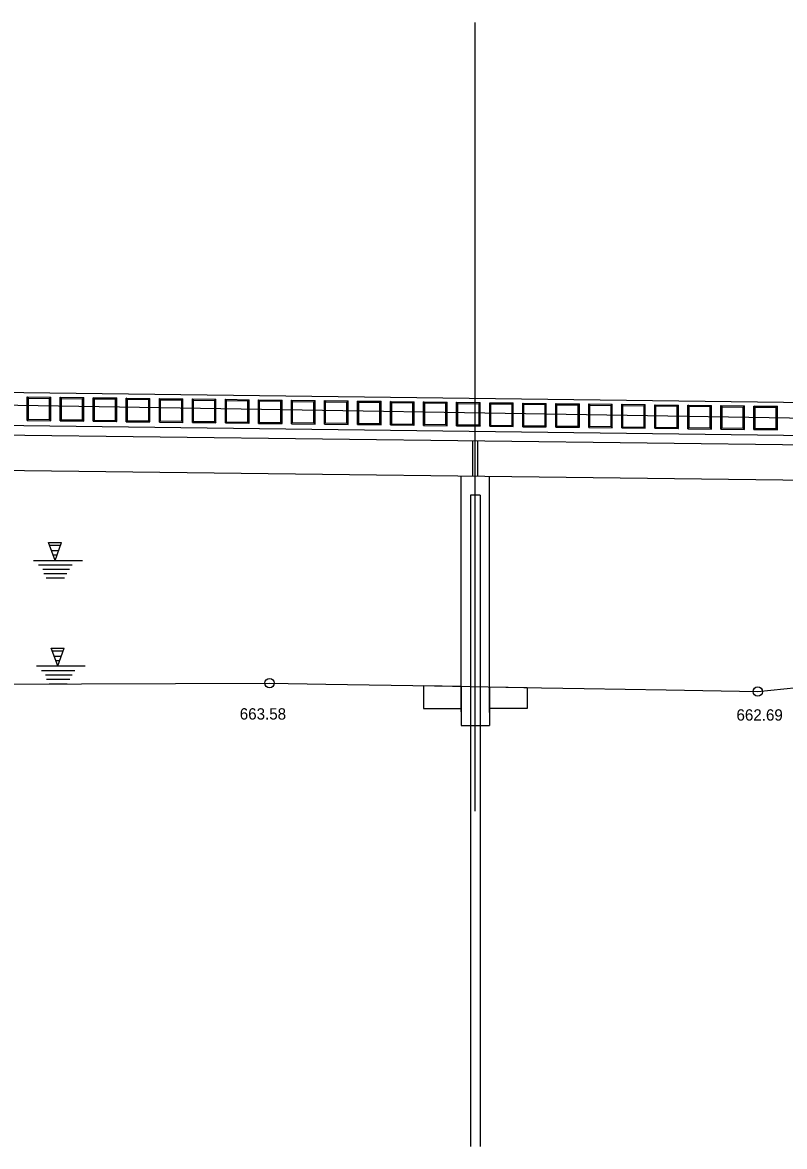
# Model space of a CAD drawing. Extents: x -845213 to 595816, y -257022 to 229056.
# Drawn here: x 595562.8 to 595643.5, y 228641.3 to 228760.5 of the extents above; entities that cross this region are included whole.
import ezdxf

# ---------------------------------------------------------------- set-up
doc = ezdxf.new("R2010")
doc.units = 0
for name, color, linetype in [('B_CL', 7, 'Continuous'), ('B_CONC', 7, 'Continuous'), ('B_CONC_HIDDEN', 7, 'Continuous'), ('B_GROUNDLINE', 7, 'Continuous'), ('B_MISC', 7, 'Continuous'), ('B_PATTERN', 7, 'Continuous'), ('B_PILES_HIDDEN', 7, 'Continuous'), ('B_SCREEN', 7, 'Continuous'), ('E_STRUCT', 7, 'Continuous'), ('P_E_PROF', 7, 'Continuous'), ('P_PROF', 7, 'Continuous')]:
    doc.layers.add(name, color=color, linetype=linetype)

msp = doc.modelspace()

# ---------------------------------------------------------------- linework, layer by layer
at = {"layer": 'B_CL'}
msp.add_line((595610.79, 228676.87), (595610.79, 228760.49), dxfattribs=at)
at = {"layer": 'B_CONC'}
for p, q in [((595399.25, 228723.31), (595719.75, 228719.29)), ((595421.62, 228718.53), (595696.95, 228715.07)), ((595610.52, 228712.41), (595610.52, 228716.16)), ((595611.06, 228712.4), (595611.06, 228716.15)), ((595417.81, 228714.82), (595700.75, 228711.28)), ((595609.29, 228687.41), (595609.29, 228712.39)), ((595612.29, 228687.35), (595612.29, 228712.36))]:
    msp.add_line(p, q, dxfattribs=at)
at = {"layer": 'B_CONC_HIDDEN'}
for p, q in [((595609.29, 228690.1), (595609.29, 228685.97)), ((595612.29, 228690.05), (595612.29, 228685.97)), ((595609.29, 228685.97), (595612.29, 228685.97))]:
    msp.add_line(p, q, dxfattribs=at)
at = {"layer": 'B_GROUNDLINE'}
for p, q in [((595566.26, 228703.47), (595565.58, 228705.35)), ((595565.58, 228705.35), (595566.95, 228705.35)), ((595565.68, 228705.08), (595566.85, 228705.08)), ((595566.26, 228703.47), (595566.95, 228705.35)), ((595565.89, 228704.5), (595566.61, 228704.5)), ((595566.07, 228704.05), (595566.47, 228704.05)), ((595563.99, 228703.47), (595569.18, 228703.47)), ((595564.52, 228703), (595568.07, 228703)), ((595564.96, 228702.53), (595567.8, 228702.53)), ((595565.06, 228702.06), (595567.52, 228702.06)), ((595565.33, 228701.6), (595567.25, 228701.6)), ((595566.55, 228692.27), (595565.86, 228694.15)), ((595565.86, 228694.15), (595567.23, 228694.15)), ((595565.96, 228693.88), (595567.13, 228693.88)), ((595566.17, 228693.3), (595566.9, 228693.3)), ((595566.55, 228692.27), (595567.23, 228694.15)), ((595564.28, 228692.27), (595569.46, 228692.27)), ((595566.36, 228692.85), (595566.75, 228692.85)), ((595564.81, 228691.8), (595568.35, 228691.8)), ((595565.25, 228691.33), (595568.08, 228691.33)), ((595565.35, 228690.86), (595567.81, 228690.86)), ((595565.62, 228690.39), (595567.54, 228690.39))]:
    msp.add_line(p, q, dxfattribs=at)
at = {"layer": 'B_MISC'}
for centre in [(595588.99, 228690.45), (595640.72, 228689.56)]:
    msp.add_circle(centre, 0.5, dxfattribs=at)
at = {"layer": 'B_PATTERN'}
for points in [[(595609.29, 228690.1), (595605.29, 228690.17), (595605.29, 228687.76), (595609.29, 228687.77)], [(595612.29, 228687.77), (595612.29, 228690.05), (595616.29, 228689.98), (595616.29, 228687.77)]]:
    msp.add_lwpolyline(points, close=True, dxfattribs=at)
at = {"layer": 'B_PILES_HIDDEN'}
for p, q in [((595610.29, 228710.4), (595611.29, 228710.4)), ((595610.29, 228710.37), (595610.29, 228641.33)), ((595611.29, 228710.37), (595611.29, 228641.33))]:
    msp.add_line(p, q, dxfattribs=at)
at = {"layer": 'B_SCREEN'}
for p, q in [((595563.31, 228718.3), (595563.31, 228720.8)), ((595563.31, 228720.8), (595565.81, 228720.77)), ((595563.43, 228720.67), (595563.31, 228720.8)), ((595563.43, 228720.67), (595565.68, 228720.64)), ((595563.43, 228718.42), (595563.43, 228720.67)), ((595565.68, 228720.64), (595565.81, 228720.77)), ((595565.68, 228718.39), (595565.68, 228720.64)), ((595565.81, 228718.27), (595565.81, 228720.77)), ((595566.81, 228718.26), (595566.81, 228720.76)), ((595566.81, 228720.76), (595569.31, 228720.72)), ((595566.93, 228720.63), (595566.81, 228720.76)), ((595566.93, 228720.63), (595569.18, 228720.6)), ((595566.93, 228718.38), (595566.93, 228720.63)), ((595569.18, 228720.6), (595569.31, 228720.72)), ((595569.18, 228718.35), (595569.18, 228720.6)), ((595569.31, 228718.22), (595569.31, 228720.72)), ((595570.31, 228718.21), (595570.31, 228720.71)), ((595570.31, 228720.71), (595572.81, 228720.68)), ((595570.43, 228720.58), (595570.31, 228720.71)), ((595570.43, 228720.58), (595572.68, 228720.56)), ((595570.43, 228718.34), (595570.43, 228720.58)), ((595572.68, 228720.56), (595572.81, 228720.68)), ((595572.68, 228718.31), (595572.68, 228720.56)), ((595572.81, 228718.18), (595572.81, 228720.68)), ((595573.81, 228718.17), (595573.81, 228720.67)), ((595573.81, 228720.67), (595576.31, 228720.64)), ((595573.93, 228720.54), (595573.81, 228720.67)), ((595573.93, 228720.54), (595576.18, 228720.51)), ((595573.93, 228718.29), (595573.93, 228720.54)), ((595576.18, 228720.51), (595576.31, 228720.64)), ((595576.18, 228718.26), (595576.18, 228720.51)), ((595576.31, 228718.14), (595576.31, 228720.64)), ((595577.31, 228718.12), (595577.31, 228720.62)), ((595577.31, 228720.62), (595579.81, 228720.59)), ((595577.43, 228720.5), (595577.31, 228720.62)), ((595577.43, 228720.5), (595579.68, 228720.47)), ((595577.43, 228718.25), (595577.43, 228720.5)), ((595579.68, 228720.47), (595579.81, 228720.59)), ((595579.68, 228718.22), (595579.68, 228720.47)), ((595579.81, 228718.09), (595579.81, 228720.59)), ((595580.81, 228718.08), (595580.81, 228720.58)), ((595580.81, 228720.58), (595583.31, 228720.55)), ((595580.93, 228720.45), (595580.81, 228720.58)), ((595580.93, 228720.45), (595583.18, 228720.43)), ((595580.93, 228718.2), (595580.93, 228720.45)), ((595583.18, 228720.43), (595583.31, 228720.55)), ((595583.31, 228718.05), (595583.31, 228720.55)), ((595584.31, 228718.04), (595584.31, 228720.54)), ((595584.31, 228720.54), (595586.81, 228720.5)), ((595584.43, 228720.41), (595584.31, 228720.54)), ((595586.68, 228720.38), (595586.81, 228720.5)), ((595586.81, 228718), (595586.81, 228720.5)), ((595587.81, 228717.99), (595587.81, 228720.49)), ((595587.81, 228720.49), (595590.31, 228720.46)), ((595587.93, 228720.37), (595587.81, 228720.49)), ((595590.18, 228720.34), (595590.31, 228720.46)), ((595590.31, 228717.96), (595590.31, 228720.46)), ((595591.31, 228717.95), (595591.31, 228720.45)), ((595591.31, 228720.45), (595593.81, 228720.42)), ((595591.43, 228720.32), (595591.31, 228720.45)), ((595583.18, 228718.18), (595583.18, 228720.43)), ((595584.43, 228720.41), (595586.68, 228720.38)), ((595584.43, 228718.16), (595584.43, 228720.41)), ((595586.68, 228718.13), (595586.68, 228720.38)), ((595587.93, 228720.37), (595590.18, 228720.34)), ((595587.93, 228718.12), (595587.93, 228720.37)), ((595590.18, 228718.09), (595590.18, 228720.34)), ((595591.43, 228720.32), (595593.68, 228720.29)), ((595591.43, 228718.07), (595591.43, 228720.32)), ((595593.68, 228720.29), (595593.81, 228720.42)), ((595593.68, 228718.04), (595593.68, 228720.29)), ((595593.81, 228717.92), (595593.81, 228720.42)), ((595594.81, 228717.9), (595594.81, 228720.4)), ((595594.81, 228720.4), (595597.31, 228720.37)), ((595594.81, 228720.4), (595594.93, 228720.28)), ((595594.93, 228720.28), (595597.18, 228720.25)), ((595594.93, 228718.03), (595594.93, 228720.28)), ((595597.18, 228720.25), (595597.31, 228720.37)), ((595597.18, 228718), (595597.18, 228720.25)), ((595597.31, 228717.87), (595597.31, 228720.37)), ((595598.31, 228717.86), (595598.31, 228720.36)), ((595598.31, 228720.36), (595600.81, 228720.33)), ((595598.43, 228720.23), (595598.31, 228720.36)), ((595598.43, 228720.23), (595600.68, 228720.21)), ((595598.43, 228717.98), (595598.43, 228720.23)), ((595600.68, 228720.21), (595600.81, 228720.33)), ((595600.68, 228717.96), (595600.68, 228720.21)), ((595600.81, 228717.83), (595600.81, 228720.33)), ((595601.81, 228717.82), (595601.81, 228720.32)), ((595601.81, 228720.32), (595604.31, 228720.29)), ((595601.93, 228720.19), (595601.81, 228720.32)), ((595601.93, 228720.19), (595604.18, 228720.16)), ((595601.93, 228717.94), (595601.93, 228720.19)), ((595604.18, 228720.16), (595604.31, 228720.29)), ((595604.18, 228717.91), (595604.18, 228720.16)), ((595604.31, 228717.79), (595604.31, 228720.29)), ((595605.31, 228717.77), (595605.31, 228720.27)), ((595605.31, 228720.27), (595607.81, 228720.24)), ((595605.43, 228720.15), (595605.31, 228720.27)), ((595605.43, 228720.15), (595607.68, 228720.12)), ((595605.43, 228717.9), (595605.43, 228720.15)), ((595607.68, 228720.12), (595607.81, 228720.24)), ((595607.68, 228717.87), (595607.68, 228720.12)), ((595607.81, 228717.74), (595607.81, 228720.24)), ((595608.81, 228717.73), (595608.81, 228720.23)), ((595608.81, 228720.23), (595611.31, 228720.2)), ((595608.93, 228720.1), (595608.81, 228720.23)), ((595608.93, 228720.1), (595611.18, 228720.07)), ((595608.93, 228717.85), (595608.93, 228720.1)), ((595611.18, 228720.07), (595611.31, 228720.2)), ((595611.18, 228717.82), (595611.18, 228720.07)), ((595611.31, 228717.7), (595611.31, 228720.2)), ((595612.31, 228717.68), (595612.31, 228720.18)), ((595612.31, 228720.18), (595614.81, 228720.15)), ((595612.43, 228720.06), (595612.31, 228720.18)), ((595612.43, 228720.06), (595614.68, 228720.03)), ((595612.43, 228717.81), (595612.43, 228720.06)), ((595614.68, 228720.03), (595614.81, 228720.15)), ((595614.68, 228717.78), (595614.68, 228720.03)), ((595614.81, 228717.65), (595614.81, 228720.15)), ((595615.81, 228717.64), (595615.81, 228720.14)), ((595615.81, 228720.14), (595618.31, 228720.11)), ((595615.93, 228720.01), (595615.81, 228720.14)), ((595615.93, 228720.01), (595618.18, 228719.99)), ((595615.93, 228717.76), (595615.93, 228720.01)), ((595618.18, 228719.99), (595618.31, 228720.11)), ((595618.18, 228717.74), (595618.18, 228719.99)), ((595618.31, 228717.61), (595618.31, 228720.11)), ((595619.31, 228717.6), (595619.31, 228720.1)), ((595619.31, 228720.1), (595621.81, 228720.07)), ((595619.43, 228719.97), (595619.31, 228720.1)), ((595619.43, 228719.97), (595621.68, 228719.94)), ((595619.43, 228717.72), (595619.43, 228719.97)), ((595621.68, 228719.94), (595621.81, 228720.07)), ((595621.68, 228717.69), (595621.68, 228719.94)), ((595621.81, 228717.57), (595621.81, 228720.07)), ((595622.81, 228717.55), (595622.81, 228720.05)), ((595622.81, 228720.05), (595625.3, 228720.02)), ((595622.93, 228719.93), (595622.81, 228720.05)), ((595622.93, 228719.93), (595625.18, 228719.9)), ((595622.93, 228717.68), (595622.93, 228719.93)), ((595625.18, 228719.9), (595625.3, 228720.02)), ((595625.18, 228717.65), (595625.18, 228719.9)), ((595625.3, 228717.52), (595625.3, 228720.02)), ((595626.3, 228717.51), (595626.3, 228720.01)), ((595626.3, 228720.01), (595628.8, 228719.98)), ((595626.43, 228719.88), (595626.3, 228720.01)), ((595626.43, 228719.88), (595628.68, 228719.85)), ((595626.43, 228717.63), (595626.43, 228719.88)), ((595628.68, 228719.85), (595628.8, 228719.98)), ((595628.68, 228717.6), (595628.68, 228719.85)), ((595628.8, 228717.48), (595628.8, 228719.98)), ((595629.8, 228717.47), (595629.8, 228719.97)), ((595629.8, 228719.97), (595632.3, 228719.93)), ((595629.93, 228719.84), (595629.8, 228719.97)), ((595629.93, 228719.84), (595632.18, 228719.81)), ((595629.93, 228717.59), (595629.93, 228719.84)), ((595632.18, 228719.81), (595632.3, 228719.93)), ((595632.18, 228717.56), (595632.18, 228719.81)), ((595632.3, 228717.43), (595632.3, 228719.93)), ((595633.3, 228717.42), (595633.3, 228719.92)), ((595633.3, 228719.92), (595635.8, 228719.89)), ((595633.43, 228719.8), (595633.3, 228719.92)), ((595633.43, 228719.8), (595635.68, 228719.77)), ((595633.43, 228717.55), (595633.43, 228719.8)), ((595635.68, 228719.77), (595635.8, 228719.89)), ((595635.68, 228717.52), (595635.68, 228719.77)), ((595635.8, 228717.39), (595635.8, 228719.89)), ((595636.8, 228717.38), (595636.8, 228719.88)), ((595636.93, 228719.75), (595636.8, 228719.88)), ((595636.8, 228719.88), (595639.3, 228719.85)), ((595636.93, 228717.5), (595636.93, 228719.75)), ((595636.93, 228719.75), (595639.18, 228719.72)), ((595639.18, 228719.72), (595639.3, 228719.85)), ((595639.18, 228717.47), (595639.18, 228719.72)), ((595639.3, 228717.35), (595639.3, 228719.85)), ((595640.3, 228717.33), (595640.3, 228719.83)), ((595640.3, 228719.83), (595642.8, 228719.8)), ((595640.43, 228719.71), (595640.3, 228719.83)), ((595640.43, 228719.71), (595642.68, 228719.68)), ((595640.43, 228717.46), (595640.43, 228719.71)), ((595642.68, 228719.68), (595642.8, 228719.8)), ((595642.68, 228717.43), (595642.68, 228719.68)), ((595642.8, 228717.3), (595642.8, 228719.8)), ((595563.31, 228718.3), (595563.43, 228718.42)), ((595563.31, 228718.3), (595565.81, 228718.27)), ((595563.43, 228718.42), (595565.68, 228718.39)), ((595565.68, 228718.39), (595565.81, 228718.27)), ((595566.81, 228718.26), (595566.93, 228718.38)), ((595566.81, 228718.26), (595569.31, 228718.22)), ((595566.93, 228718.38), (595569.18, 228718.35)), ((595569.18, 228718.35), (595569.31, 228718.22)), ((595570.31, 228718.21), (595570.43, 228718.34)), ((595570.31, 228718.21), (595572.81, 228718.18)), ((595570.43, 228718.34), (595572.68, 228718.31)), ((595572.68, 228718.31), (595572.81, 228718.18)), ((595573.81, 228718.17), (595573.93, 228718.29)), ((595573.81, 228718.17), (595576.31, 228718.14)), ((595573.93, 228718.29), (595576.18, 228718.26)), ((595576.18, 228718.26), (595576.31, 228718.14)), ((595577.31, 228718.12), (595577.43, 228718.25)), ((595577.31, 228718.12), (595579.81, 228718.09)), ((595577.43, 228718.25), (595579.68, 228718.22)), ((595579.68, 228718.22), (595579.81, 228718.09)), ((595580.81, 228718.08), (595580.93, 228718.2)), ((595580.81, 228718.08), (595583.31, 228718.05)), ((595580.93, 228718.2), (595583.18, 228718.18)), ((595583.18, 228718.18), (595583.31, 228718.05)), ((595584.31, 228718.04), (595584.43, 228718.16)), ((595584.43, 228718.16), (595586.68, 228718.13)), ((595586.68, 228718.13), (595586.81, 228718)), ((595587.81, 228717.99), (595587.93, 228718.12)), ((595587.93, 228718.12), (595590.18, 228718.09)), ((595590.18, 228718.09), (595590.31, 228717.96)), ((595591.31, 228717.95), (595591.43, 228718.07)), ((595591.43, 228718.07), (595593.68, 228718.04)), ((595584.31, 228718.04), (595586.81, 228718)), ((595587.81, 228717.99), (595590.31, 228717.96)), ((595591.31, 228717.95), (595593.81, 228717.92)), ((595593.68, 228718.04), (595593.81, 228717.92)), ((595594.81, 228717.9), (595594.93, 228718.03)), ((595594.81, 228717.9), (595597.31, 228717.87)), ((595594.93, 228718.03), (595597.18, 228718)), ((595597.18, 228718), (595597.31, 228717.87)), ((595598.31, 228717.86), (595598.43, 228717.98)), ((595598.31, 228717.86), (595600.81, 228717.83)), ((595598.43, 228717.98), (595600.68, 228717.96)), ((595600.68, 228717.96), (595600.81, 228717.83)), ((595601.81, 228717.82), (595601.93, 228717.94)), ((595601.81, 228717.82), (595604.31, 228717.79)), ((595601.93, 228717.94), (595604.18, 228717.91)), ((595604.18, 228717.91), (595604.31, 228717.79)), ((595605.31, 228717.77), (595605.43, 228717.9)), ((595605.31, 228717.77), (595607.81, 228717.74)), ((595605.43, 228717.9), (595607.68, 228717.87)), ((595607.68, 228717.87), (595607.81, 228717.74)), ((595608.81, 228717.73), (595608.93, 228717.85)), ((595608.81, 228717.73), (595611.31, 228717.7)), ((595608.93, 228717.85), (595611.18, 228717.82)), ((595611.18, 228717.82), (595611.31, 228717.7)), ((595612.31, 228717.68), (595612.43, 228717.81)), ((595612.31, 228717.68), (595614.81, 228717.65)), ((595612.43, 228717.81), (595614.68, 228717.78)), ((595614.68, 228717.78), (595614.81, 228717.65)), ((595615.81, 228717.64), (595615.93, 228717.76)), ((595615.81, 228717.64), (595618.31, 228717.61)), ((595615.93, 228717.76), (595618.18, 228717.74)), ((595618.18, 228717.74), (595618.31, 228717.61)), ((595619.31, 228717.6), (595619.43, 228717.72)), ((595619.31, 228717.6), (595621.81, 228717.57)), ((595619.43, 228717.72), (595621.68, 228717.69)), ((595621.68, 228717.69), (595621.81, 228717.57)), ((595622.81, 228717.55), (595622.93, 228717.68)), ((595622.81, 228717.55), (595625.3, 228717.52)), ((595622.93, 228717.68), (595625.18, 228717.65)), ((595625.18, 228717.65), (595625.3, 228717.52)), ((595626.3, 228717.51), (595626.43, 228717.63)), ((595626.3, 228717.51), (595628.8, 228717.48)), ((595626.43, 228717.63), (595628.68, 228717.6)), ((595628.68, 228717.6), (595628.8, 228717.48)), ((595629.8, 228717.47), (595629.93, 228717.59)), ((595629.8, 228717.47), (595632.3, 228717.43)), ((595629.93, 228717.59), (595632.18, 228717.56)), ((595632.18, 228717.56), (595632.3, 228717.43)), ((595633.3, 228717.42), (595633.43, 228717.55)), ((595633.3, 228717.42), (595635.8, 228717.39)), ((595633.43, 228717.55), (595635.68, 228717.52)), ((595635.68, 228717.52), (595635.8, 228717.39)), ((595636.8, 228717.38), (595636.93, 228717.5)), ((595636.8, 228717.38), (595639.3, 228717.35)), ((595636.93, 228717.5), (595639.18, 228717.47)), ((595639.18, 228717.47), (595639.3, 228717.35)), ((595640.3, 228717.33), (595640.43, 228717.46)), ((595640.3, 228717.33), (595642.8, 228717.3)), ((595640.43, 228717.46), (595642.68, 228717.43)), ((595642.68, 228717.43), (595642.8, 228717.3))]:
    msp.add_line(p, q, dxfattribs=at)
at = {"layer": 'E_STRUCT'}
msp.add_line((595399.35, 228722.55), (595731.51, 228717.17), dxfattribs=at)
at = {"layer": 'P_E_PROF'}
for p, q in [((595640.72, 228689.56), (595651.04, 228690.66)), ((595553.36, 228690.32), (595569.07, 228690.38)), ((595569.07, 228690.38), (595588.99, 228690.45)), ((595588.99, 228690.45), (595594.96, 228690.35)), ((595594.96, 228690.35), (595606.46, 228690.15)), ((595606.46, 228690.15), (595617.81, 228689.95)), ((595617.81, 228689.95), (595622.33, 228689.88)), ((595622.33, 228689.88), (595631, 228689.73)), ((595631, 228689.73), (595640.72, 228689.56))]:
    msp.add_line(p, q, dxfattribs=at)
at = {"layer": 'P_PROF'}
msp.add_line((595315.56, 228720.86), (595815.56, 228714.59), dxfattribs=at)

# ---------------------------------------------------------------- texts
at = {"layer": 'B_MISC'}
for s, p in [('663.58', (595585.83, 228686.59)), ('662.69', (595638.46, 228686.48))]:
    msp.add_text(s, height=1.2, dxfattribs=at).set_placement(p)

doc.saveas('drawing.dxf')
